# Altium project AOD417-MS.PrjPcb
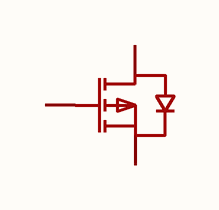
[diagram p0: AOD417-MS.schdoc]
1 sheet, 1 parts. Net scope: global (net labels, ports and power ports of the same name join across sheets).

## Sheet AOD417-MS.schdoc
size 127 x 101 mm

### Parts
Q?  aod417-ms  [TO-252-3_L6.6-W6.1-P4.57-LS9.9-BR-CW]  (value not drawn)

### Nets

Not connected (* = marked no-connect by the designer): Q? 1(G) 2(D) 3(S)

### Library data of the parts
Q? = aod417-ms: 数量:1个P沟道;漏源电压(Vdss):30V;连续漏极电流(Id):40A;导通电阻(RDS(on)):18mΩ@10V;耗散功率(Pd):34.7W;阈值电压(Vgs(th)):2.5V;; Manufacturer: MSKSEMI(美森科); AddInBom: yes; ModelId: dee852f3c6b348a2b9d5be5dd3244081; ModelTransform: 258.97184,390.1567,0,90,0,0,-35.433,0,0; Number: 1个P沟道; Drain to Source Voltage: 30V; Current - Continuous Drain(Id): 40A; Pd - Power Dissipation: 34.7W; Gate Threshold Voltage (Vgs(th)): 2.5V; Gate Charge(Qg): 12.5nC@4.5V; Input Capacitance(Ciss): 1.345nF; Reverse Transfer Capacitance (Crss@Vds): 158pF; Type: P沟道; Output Capacitance(Coss): 194pF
